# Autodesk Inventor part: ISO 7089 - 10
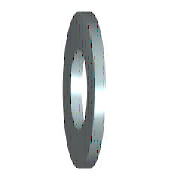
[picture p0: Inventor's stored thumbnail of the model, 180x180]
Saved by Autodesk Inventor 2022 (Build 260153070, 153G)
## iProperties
Created: 2021-02
Part Number: ISO 7089 - 10
Material: Acier inoxydable
Description: Rondelles plates - Série standard - Produit de classe A
Document SubType Name: Modeling
Standard: ISO 7089
Designer: Fabian
Standard Revision: Second edition 2000-06-01
Standards Organization: ISO
Language: fr-FR
Size Designation: 10
Categories: <MemberInstance><Categories><Category DisplayName="Visserie" InternalName="e4da775c-781d-43d5-af7c-5136215cf5a6" Mnemonic="FSTN"><Category DisplayName="Rondelle
Density: 8 g/cm^3
Appearance: Semi-poli
IsCustomPart: 0
Author: Fabian
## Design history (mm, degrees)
sketch "Esquisse"
  geometry: C1 r 10 at (0, 0); C2 r 5.25 at (0, 0); 1 further point
  constraints: 2 centre point, 2 coincident
  dimensions: "d0" = 10.5 diameter of C2 (= SD1); "d1" = 20 diameter of C1 (= SD2)
extrude "Corps" new body sketch "Esquisse" distance "d2" = 2 (= SD); taper "d3" = 0 deg
workaxis "Work Axis1"
workplane "Work Plane1"
body "Solid1"
other parameters: "SD1" = 10.5 [user parameter; used in 1 equation term], "SD2" = 20 [user parameter; used in 1 equation term], "SD" = 2 [user parameter; used in 1 equation term], "d4" = 0, "d5" = 0, "d6" = 0, "d7" = 0
